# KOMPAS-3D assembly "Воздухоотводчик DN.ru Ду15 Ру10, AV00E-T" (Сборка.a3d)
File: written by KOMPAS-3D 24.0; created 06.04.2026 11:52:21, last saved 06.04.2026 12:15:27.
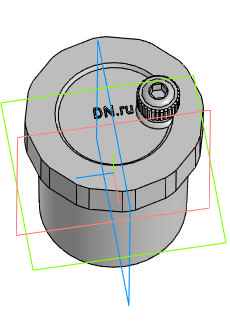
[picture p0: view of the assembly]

Document properties: Автор: R2D2; Полное имя файла: E:\Работа\Зайцев\Солянка\AV00E-T Воздухоотводчик DN.ru\Ду15 Ру10\исходные материалы\Сборка.a3d

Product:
- Component [detail]: VT.502.NV.04  | qty 1  | pos. 1  | Масса: 0.482559; Автор: R2D2; additional columns: Типовые; source file: 1.m3d
- Component [detail]: VT.502.NV.04  | qty 1  | pos. 1  | Масса: 0.003903; Автор: R2D2; additional columns: Типовые; source file: 2.m3d
- Part/product: Воздухоотводчик DN.ru Ду15 Ру10  | designation AV00E-T
    Масса: 0.13
    Раздел спецификации: Прочие изделия
    Примечание: D030-00297

Referenced files in E:\Работа\Зайцев\Солянка\AV00E-T Воздухоотводчик DN.ru\Ду15 Ру10\исходные материалы\: 1.m3d, 2.m3d
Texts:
  AV00E-T
  VT.502.NV.04 VT.502.NV.04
